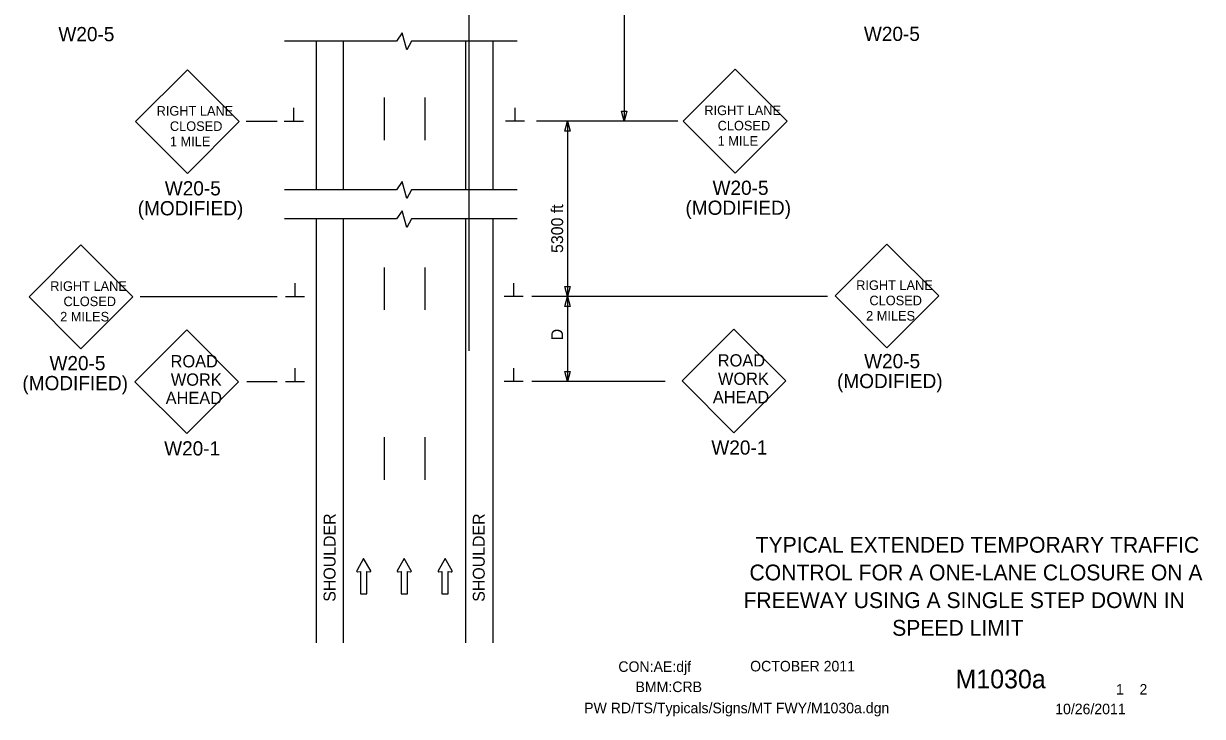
# Model space of a CAD drawing. Extents: x 16740 to 18479, y 5932 to 6964.
# Drawn here: x 16740 to 17435, y 5932 to 6340 of the extents above; entities that cross this region are included whole.
import ezdxf

# ---------------------------------------------------------------- set-up
doc = ezdxf.new("R2010")
doc.units = 0
for name, color, linetype in [('ALI_LEGAL_EX', 7, 'Continuous'), ('BORDER', 7, 'Continuous'), ('BORDER_SIGNAL_WO', 7, 'Continuous'), ('MT_SCRATCH_LEVEL_E', 7, 'Continuous'), ('PAVT_EDGE_EX', 7, 'Continuous'), ('TRAFFIC_SIGNS_PR', 7, 'Continuous'), ('TYPICAL_TEXT_DIMEN_PR', 7, 'Continuous')]:
    doc.layers.add(name, color=color, linetype=linetype)

msp = doc.modelspace()

# ---------------------------------------------------------------- linework, layer by layer
at = {"layer": 'ALI_LEGAL_EX'}
msp.add_line((17002.72, 6964.07), (17002.72, 6147.1), dxfattribs=at)
for points in [[(16952.72, 6296.22), (16952.72, 6271.22)], [(16976.72, 6296.22), (16976.72, 6271.22)], [(16952.72, 6196.22), (16952.72, 6171.22)], [(16976.72, 6196.22), (16976.72, 6171.22)], [(16952.72, 6096.22), (16952.72, 6071.22)], [(16976.72, 6096.22), (16976.72, 6071.22)]]:
    msp.add_lwpolyline(points, dxfattribs=at)
at = {"layer": 'MT_SCRATCH_LEVEL_E'}
for p, q in [((16940.72, 6024.82), (16936.61, 6017.57)), ((16944.87, 6017.57), (16940.72, 6024.82)), ((16964.62, 6024.82), (16960.51, 6017.57)), ((16968.77, 6017.57), (16964.62, 6024.82)), ((16988.68, 6024.82), (16984.56, 6017.57)), ((16992.82, 6017.57), (16988.68, 6024.82)), ((16937.09, 6016.89), (16938.87, 6017.21)), ((16938.87, 6017.21), (16938.87, 6003.95)), ((16942.61, 6003.95), (16942.61, 6017.21)), ((16942.61, 6017.21), (16944.39, 6016.89)), ((16960.99, 6016.89), (16962.77, 6017.21)), ((16962.77, 6017.21), (16962.77, 6003.95)), ((16966.51, 6003.95), (16966.51, 6017.21)), ((16966.51, 6017.21), (16968.29, 6016.89)), ((16985.05, 6016.89), (16986.82, 6017.21)), ((16986.82, 6017.21), (16986.82, 6003.95)), ((16990.57, 6003.95), (16990.57, 6017.21)), ((16990.57, 6017.21), (16992.34, 6016.89)), ((16938.87, 6003.95), (16942.61, 6003.95)), ((16962.77, 6003.95), (16966.51, 6003.95)), ((16986.82, 6003.95), (16990.57, 6003.95))]:
    msp.add_line(p, q, dxfattribs=at)
for centre, start, end in [((16937.02, 6017.35), 150.42484, 279.96381), ((16944.46, 6017.35), 260.03619, 29.77312), ((16960.92, 6017.35), 150.42484, 279.96381), ((16968.36, 6017.35), 260.03619, 29.77312), ((16984.97, 6017.35), 150.42484, 279.96381), ((16992.41, 6017.35), 260.03619, 29.77312)]:
    msp.add_arc(centre, 0.463, start, end, dxfattribs=at)
at = {"layer": 'PAVT_EDGE_EX'}
for p, q in [((16912.72, 6329.5), (16912.72, 6242.36)), ((16928.72, 6329.5), (16928.72, 6242.36)), ((17000.72, 6329.5), (17000.72, 6241.77)), ((17016.72, 6329.5), (17016.72, 6241.94)), ((16912.72, 6224.8), (16912.72, 5975.18)), ((16928.72, 6224.8), (16928.72, 5975.18)), ((17000.72, 6224.8), (17000.72, 5975.18)), ((17016.72, 6224.8), (17016.72, 5975.18))]:
    msp.add_line(p, q, dxfattribs=at)
at = {"layer": 'TRAFFIC_SIGNS_PR'}
for p, q in [((16836.92, 6312.58), (16806.38, 6282.03)), ((16867.47, 6282.03), (16836.92, 6312.58)), ((17159.46, 6312.88), (17128.92, 6282.33)), ((17190.01, 6282.33), (17159.46, 6312.88)), ((17128.92, 6282.33), (17159.46, 6251.78)), ((17159.46, 6251.78), (17190.01, 6282.33)), ((16806.38, 6282.03), (16836.92, 6251.48)), ((16836.92, 6251.48), (16867.47, 6282.03)), ((16774.27, 6209.41), (16743.73, 6178.86)), ((16804.82, 6178.86), (16774.27, 6209.41)), ((17248.85, 6209.94), (17218.31, 6179.39)), ((17279.4, 6179.39), (17248.85, 6209.94)), ((16743.73, 6178.86), (16774.27, 6148.31)), ((16774.27, 6148.31), (16804.82, 6178.86)), ((17218.31, 6179.39), (17248.85, 6148.85)), ((17248.85, 6148.85), (17279.4, 6179.39)), ((16836.56, 6159.43), (16806.01, 6128.88)), ((16867.11, 6128.88), (16836.56, 6159.43)), ((17158.76, 6159.94), (17128.22, 6129.39)), ((17189.31, 6129.39), (17158.76, 6159.94)), ((16806.01, 6128.88), (16836.56, 6098.34)), ((16836.56, 6098.34), (16867.11, 6128.88)), ((17128.22, 6129.39), (17158.76, 6098.84)), ((17158.76, 6098.84), (17189.31, 6129.39))]:
    msp.add_line(p, q, dxfattribs=at)
at = {"layer": 'TYPICAL_TEXT_DIMEN_PR'}
for p, q in [((17094.11, 6623.15), (17094.11, 6282.38)), ((16963.32, 6334.3), (16960.07, 6329.5)), ((16966.07, 6324.36), (16963.32, 6334.3)), ((16960.07, 6329.5), (16894.13, 6329.5)), ((16968.81, 6329.5), (16966.07, 6324.36)), ((17031.14, 6329.5), (16968.81, 6329.5)), ((16899.6, 6282.38), (16899.6, 6290.17)), ((17029.85, 6282.38), (17029.85, 6290.17)), ((16871.56, 6282.38), (16889.72, 6282.38)), ((16893.97, 6282.38), (16905.22, 6282.38)), ((17035.47, 6282.38), (17024.22, 6282.38)), ((17125.75, 6282.38), (17042.57, 6282.38)), ((17059.15, 6276.52), (17060.72, 6282.38)), ((17060.72, 6282.38), (17060.72, 6129.07)), ((17060.72, 6282.38), (17062.29, 6276.52)), ((17094.11, 6282.38), (17092.53, 6288.24)), ((17092.53, 6288.24), (17094.11, 6288.24)), ((17094.11, 6288.24), (17095.68, 6288.24)), ((17095.68, 6288.24), (17094.11, 6282.38)), ((17060.72, 6276.52), (17059.15, 6276.52)), ((17062.29, 6276.52), (17060.72, 6276.52)), ((16960.07, 6241.94), (16894.13, 6241.94)), ((16963.32, 6246.74), (16960.07, 6241.94)), ((16966.07, 6236.8), (16963.32, 6246.74)), ((16968.81, 6241.94), (16966.07, 6236.8)), ((17031.14, 6241.94), (16968.81, 6241.94)), ((16963.32, 6229.6), (16960.07, 6224.8)), ((16966.07, 6219.66), (16963.32, 6229.6)), ((16960.07, 6224.8), (16894.13, 6224.8)), ((16968.81, 6224.8), (16966.07, 6219.66)), ((17031.14, 6224.8), (16968.81, 6224.8)), ((16900.35, 6179.07), (16900.35, 6186.85)), ((17029.1, 6179.07), (17029.1, 6186.85)), ((16809.13, 6179.07), (16889.72, 6179.07)), ((16894.72, 6179.07), (16905.97, 6179.07)), ((17034.72, 6179.07), (17023.47, 6179.07)), ((17213.78, 6179.07), (17039.72, 6179.07)), ((17060.72, 6179.07), (17059.15, 6184.93)), ((17059.15, 6184.93), (17060.72, 6184.93)), ((17059.15, 6173.21), (17060.72, 6179.07)), ((17060.72, 6184.93), (17062.29, 6184.93)), ((17062.29, 6184.93), (17060.72, 6179.07)), ((17060.72, 6179.07), (17060.72, 6129.07)), ((17060.72, 6179.07), (17062.29, 6173.21)), ((17060.72, 6173.21), (17059.15, 6173.21)), ((17062.29, 6173.21), (17060.72, 6173.21)), ((16900.35, 6129.07), (16900.35, 6136.85)), ((17029.1, 6129.07), (17029.1, 6136.85)), ((17060.72, 6129.07), (17059.15, 6134.93)), ((17059.15, 6134.93), (17060.72, 6134.93)), ((17060.72, 6134.93), (17062.29, 6134.93)), ((17062.29, 6134.93), (17060.72, 6129.07)), ((16871.95, 6129.07), (16889.72, 6129.07)), ((16894.72, 6129.07), (16905.97, 6129.07)), ((17034.72, 6129.07), (17023.47, 6129.07)), ((17118.19, 6129.07), (17039.72, 6129.07))]:
    msp.add_line(p, q, dxfattribs=at)

# ---------------------------------------------------------------- texts
at = {"layer": 'BORDER'}
for s, p in [('TYPICAL EXTENDED TEMPORARY TRAFFIC', (17171.54, 6028.24)), ('CONTROL FOR A ONE-LANE CLOSURE ON A', (17167.92, 6011.94)), (' FREEWAY USING A SINGLE STEP DOWN IN ', (17160.92, 5995.64)), ('SPEED LIMIT', (17251.92, 5979.34))]:
    msp.add_text(s, height=9.3, dxfattribs=at).set_placement(p)
at = {"layer": 'BORDER_SIGNAL_WO'}
for s, height, p in [('CON:AE:djf  ', 6.2, (17090.69, 5958.06)), ('    OCTOBER 2011    ', 6.2, (17159.08, 5958.34)), ('    M1030a   ', 11, (17272.86, 5948.38)), ('BMM:CRB   ', 6.2, (17100.81, 5946.17)), (' 1    2 ', 6.2, (17381.45, 5944.7)), ('PW RD/TS/Typicals/Signs/MT FWY/M1030a.dgn      ', 6.2, (17070.55, 5933.71)), ('10/26/2011    ', 6.2, (17347.93, 5933.13))]:
    msp.add_text(s, height=height, dxfattribs=at).set_placement(p)
at = {"layer": 'TRAFFIC_SIGNS_PR'}
for s, height, p in [('W20-5', 8.37, (16760.97, 6329.39)), ('W20-5', 8.37, (17235.28, 6329.56)), ('RIGHT LANE', 5.625, (16818.79, 6285.57)), ('RIGHT LANE', 5.625, (17141.33, 6285.88)), ('CLOSED', 5.625, (16826.62, 6276.57)), ('CLOSED', 5.625, (17149.16, 6276.88)), ('1 MILE', 5.625, (16826.61, 6267.57)), ('1 MILE', 5.625, (17149.15, 6267.88)), ('W20-5', 8.37, (16823.62, 6238.61)), ('W20-5', 8.37, (17146.16, 6238.92)), ('(MODIFIED)', 8.37, (16807.67, 6226.87)), ('(MODIFIED)', 8.37, (17130.21, 6227.17)), ('RIGHT LANE', 5.625, (16756.14, 6182.4)), ('RIGHT LANE', 5.625, (17230.72, 6182.94)), ('CLOSED', 5.625, (16763.96, 6173.4)), ('CLOSED', 5.625, (17238.54, 6173.94)), ('2 MILES', 5.625, (16762, 6164.4)), ('2 MILES', 5.625, (17236.57, 6164.94)), ('W20-5', 8.37, (16755.72, 6135.67)), ('ROAD', 7.2, (16827.04, 6137.36)), ('ROAD', 7.2, (17149.25, 6137.87)), ('W20-5', 8.37, (17235.42, 6136.86)), ('(MODIFIED)', 8.37, (16739.77, 6123.93)), ('WORK', 7.2, (16827.17, 6126.56)), ('WORK', 7.2, (17149.37, 6127.07)), ('(MODIFIED)', 8.37, (17219.47, 6125.12)), ('AHEAD', 7.2, (16824.14, 6115.76)), ('AHEAD', 7.2, (17146.34, 6116.27)), ('W20-1', 8.37, (16823.25, 6085.47)), ('W20-1', 8.37, (17145.45, 6085.97))]:
    msp.add_text(s, height=height, dxfattribs=at).set_placement(p)
at = {"layer": 'TYPICAL_TEXT_DIMEN_PR'}
for s, p in [('5300 ft', (17058.16, 6204.71)), ('D', (17058.16, 6153.29)), ('SHOULDER', (16924.14, 5999.36)), ('SHOULDER', (17012, 5999.36))]:
    msp.add_text(s, height=7, rotation=90, dxfattribs=at).set_placement(p)

doc.saveas('drawing.dxf')
